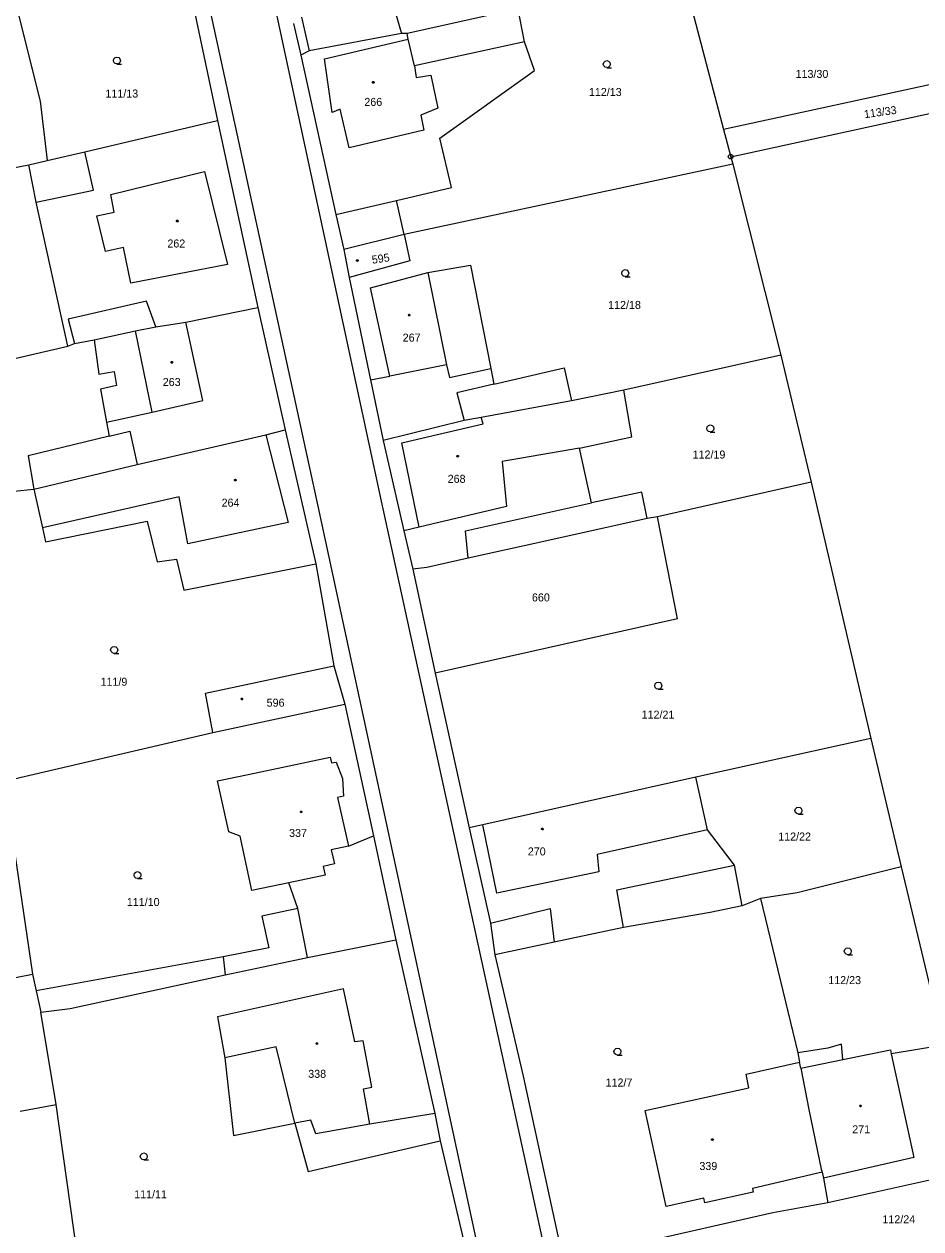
# Model space of a CAD drawing. Extents: x -757994 to -755874, y -1047691 to -1046119.
# Drawn here: x -756452.9 to -756357.8, y -1047170.3 to -1047042.4 of the extents above; entities that cross this region are included whole.
import ezdxf

# ---------------------------------------------------------------- set-up
doc = ezdxf.new("R2010")
doc.units = 0
doc.layers.add('katastrální mapa', color=7, linetype='Continuous')

msp = doc.modelspace()

# ---------------------------------------------------------------- linework, layer by layer
at = {"layer": 'katastrální mapa'}
for p, q in [((-756415, -1047093.07), (-756430.44, -1047021.1)), ((-756438.8, -1047022.23), (-756432.39, -1047052.66)), ((-756437.35, -1047021.83), (-756421.74, -1047093.61)), ((-756383.08, -1047037.05), (-756378.72, -1047053.6)), ((-756413.72, -1047040.53), (-756412.88, -1047043.43)), ((-756399.82, -1047044.31), (-756400.59, -1047040.49)), ((-756453.58, -1047041.15), (-756451.2, -1047050.59)), ((-756423.48, -1047041.7), (-756422.66, -1047045.25)), ((-756402.57, -1047041.28), (-756412.28, -1047043.41)), ((-756424.34, -1047042.36), (-756423.55, -1047045.74)), ((-756412.88, -1047043.43), (-756422.66, -1047045.25)), ((-756421.04, -1047046.13), (-756412.18, -1047044.01)), ((-756412.28, -1047043.41), (-756412.88, -1047043.43)), ((-756412.18, -1047044.01), (-756412.28, -1047043.41)), ((-756411.49, -1047046.87), (-756412.18, -1047044.01)), ((-756399.82, -1047044.31), (-756411.49, -1047046.87)), ((-756398.78, -1047047.34), (-756399.82, -1047044.31)), ((-756422.66, -1047045.25), (-756423.55, -1047045.74)), ((-756423.55, -1047045.74), (-756419.85, -1047062.65)), ((-756420.24, -1047051.8), (-756421.04, -1047046.13)), ((-756411.49, -1047046.87), (-756411.33, -1047048.08)), ((-756342.39, -1047045.7), (-756378.72, -1047053.6)), ((-756411.33, -1047048.08), (-756409.76, -1047047.84)), ((-756409.76, -1047047.84), (-756409.02, -1047051.35)), ((-756408.81, -1047054.52), (-756398.78, -1047047.34)), ((-756377.96, -1047056.5), (-756340.02, -1047048.25)), ((-756451.2, -1047050.59), (-756450.47, -1047056.91)), ((-756419.39, -1047051.46), (-756420.24, -1047051.8)), ((-756418.42, -1047055.57), (-756419.39, -1047051.46)), ((-756409.02, -1047051.35), (-756410.84, -1047052.1)), ((-756446.45, -1047056), (-756432.39, -1047052.66)), ((-756432.39, -1047052.66), (-756428.13, -1047072.51)), ((-756410.84, -1047052.1), (-756410.52, -1047053.67)), ((-756410.52, -1047053.67), (-756418.42, -1047055.57)), ((-756407.58, -1047059.77), (-756408.81, -1047054.52)), ((-756378.72, -1047053.6), (-756377.96, -1047056.5)), ((-756452.42, -1047057.35), (-756450.47, -1047056.91)), ((-756450.47, -1047056.91), (-756446.45, -1047056)), ((-756445.56, -1047060.06), (-756446.45, -1047056)), ((-756378.02, -1047056.5), (-756377.9, -1047056.5)), ((-756377.96, -1047056.5), (-756377.75, -1047057.29)), ((-756466.88, -1047060.21), (-756452.42, -1047057.35)), ((-756451.61, -1047061.33), (-756452.42, -1047057.35)), ((-756443.69, -1047060.51), (-756433.78, -1047058.06)), ((-756433.78, -1047058.06), (-756431.33, -1047067.93)), ((-756377.75, -1047057.29), (-756412.59, -1047064.77)), ((-756377.75, -1047057.29), (-756372.63, -1047077.56)), ((-756451.61, -1047061.33), (-756445.56, -1047060.06)), ((-756443.34, -1047062.4), (-756443.69, -1047060.51)), ((-756413.41, -1047061.14), (-756407.58, -1047059.77)), ((-756448.28, -1047076.61), (-756451.61, -1047061.33)), ((-756419.85, -1047062.65), (-756413.41, -1047061.14)), ((-756412.59, -1047064.77), (-756413.41, -1047061.14)), ((-756445.2, -1047062.79), (-756443.34, -1047062.4)), ((-756444.26, -1047066.58), (-756445.2, -1047062.79)), ((-756419.85, -1047062.65), (-756418.99, -1047066.35)), ((-756412.59, -1047064.77), (-756418.99, -1047066.35)), ((-756412.59, -1047064.77), (-756411.98, -1047067.55)), ((-756442.37, -1047066.15), (-756444.26, -1047066.58)), ((-756441.59, -1047069.93), (-756442.37, -1047066.15)), ((-756418.99, -1047066.35), (-756418.44, -1047069.33)), ((-756431.33, -1047067.93), (-756441.59, -1047069.93)), ((-756411.98, -1047067.55), (-756418.44, -1047069.33)), ((-756410.09, -1047068.8), (-756405.55, -1047068)), ((-756405.55, -1047068), (-756403.41, -1047078.99)), ((-756418.44, -1047069.33), (-756416.18, -1047080.19)), ((-756416.18, -1047070.43), (-756410.09, -1047068.8)), ((-756410.09, -1047068.8), (-756408.12, -1047078.58)), ((-756414.12, -1047079.78), (-756416.18, -1047070.43)), ((-756439.92, -1047071.82), (-756448.22, -1047073.75)), ((-756438.95, -1047074.57), (-756439.92, -1047071.82)), ((-756435.74, -1047074.06), (-756428.13, -1047072.51)), ((-756428.13, -1047072.51), (-756425.2, -1047085.48)), ((-756448.22, -1047073.75), (-756447.57, -1047076.33)), ((-756445.48, -1047075.95), (-756441.09, -1047074.99)), ((-756441.09, -1047074.99), (-756438.95, -1047074.57)), ((-756439.32, -1047083.61), (-756441.09, -1047074.99)), ((-756438.95, -1047074.57), (-756435.74, -1047074.06)), ((-756433.96, -1047082.39), (-756435.74, -1047074.06)), ((-756448.28, -1047076.61), (-756447.57, -1047076.33)), ((-756447.57, -1047076.33), (-756445.48, -1047075.95)), ((-756445.48, -1047075.95), (-756444.98, -1047079.57)), ((-756457.57, -1047078.78), (-756448.28, -1047076.61)), ((-756372.63, -1047077.56), (-756389.3, -1047081.3)), ((-756372.63, -1047077.56), (-756369.43, -1047091.04)), ((-756408.12, -1047078.58), (-756414.12, -1047079.78)), ((-756408.12, -1047078.58), (-756407.8, -1047079.95)), ((-756444.98, -1047079.57), (-756443.37, -1047079.29)), ((-756443.37, -1047079.29), (-756443.09, -1047080.78)), ((-756416.18, -1047080.19), (-756414.12, -1047079.78)), ((-756416.18, -1047080.19), (-756414.83, -1047086.64)), ((-756407.8, -1047079.95), (-756403.41, -1047078.99)), ((-756403.41, -1047078.99), (-756403.09, -1047080.66)), ((-756403.09, -1047080.66), (-756395.64, -1047078.92)), ((-756395.64, -1047078.92), (-756394.86, -1047082.43)), ((-756443.09, -1047080.78), (-756444.82, -1047081.17)), ((-756444.82, -1047081.17), (-756444.16, -1047084.67)), ((-756403.09, -1047080.66), (-756407, -1047081.57)), ((-756389.3, -1047081.3), (-756394.86, -1047082.43)), ((-756388.44, -1047086.25), (-756389.3, -1047081.3)), ((-756439.32, -1047083.61), (-756433.96, -1047082.39)), ((-756407, -1047081.57), (-756406.24, -1047084.52)), ((-756394.86, -1047082.43), (-756404.43, -1047084.17)), ((-756444.16, -1047084.67), (-756439.32, -1047083.61)), ((-756444.16, -1047084.67), (-756443.88, -1047086.15)), ((-756406.24, -1047084.52), (-756414.83, -1047086.64)), ((-756412.83, -1047086.89), (-756404.21, -1047084.85)), ((-756404.43, -1047084.17), (-756406.24, -1047084.52)), ((-756404.21, -1047084.85), (-756404.43, -1047084.17)), ((-756443.88, -1047086.15), (-756452.47, -1047088.24)), ((-756443.88, -1047086.15), (-756441.7, -1047085.62)), ((-756441.7, -1047085.62), (-756440.91, -1047089.19)), ((-756440.91, -1047089.19), (-756427.26, -1047086.02)), ((-756427.26, -1047086.02), (-756425.2, -1047085.48)), ((-756427.26, -1047086.02), (-756424.91, -1047095.32)), ((-756425.2, -1047085.48), (-756421.95, -1047099.73)), ((-756393.99, -1047087.45), (-756388.44, -1047086.25)), ((-756414.83, -1047086.64), (-756412.62, -1047096.2)), ((-756411, -1047095.82), (-756412.83, -1047086.89)), ((-756393.99, -1047087.45), (-756402.2, -1047088.86)), ((-756392.71, -1047093.25), (-756393.99, -1047087.45)), ((-756452.47, -1047088.24), (-756451.89, -1047091.78)), ((-756402.2, -1047088.86), (-756401.73, -1047093.64)), ((-756451.89, -1047091.78), (-756440.91, -1047089.19)), ((-756369.43, -1047091.04), (-756385.71, -1047094.72)), ((-756369.43, -1047091.04), (-756363.09, -1047118.27)), ((-756453.97, -1047092), (-756451.89, -1047091.78)), ((-756451.89, -1047091.78), (-756450.96, -1047095.89)), ((-756436.45, -1047092.6), (-756450.96, -1047095.89)), ((-756435.54, -1047097.59), (-756436.45, -1047092.6)), ((-756387.4, -1047092.11), (-756392.71, -1047093.25)), ((-756386.83, -1047094.89), (-756387.4, -1047092.11)), ((-756421.74, -1047093.61), (-756404.48, -1047173.68)), ((-756397.11, -1047175.01), (-756415, -1047093.07)), ((-756401.73, -1047093.64), (-756411, -1047095.82)), ((-756406.1, -1047096.2), (-756392.71, -1047093.25)), ((-756450.64, -1047097.38), (-756439.84, -1047095.19)), ((-756439.84, -1047095.19), (-756438.8, -1047099.5)), ((-756424.91, -1047095.32), (-756435.54, -1047097.59)), ((-756386.83, -1047094.89), (-756397.79, -1047097.35)), ((-756385.71, -1047094.72), (-756386.83, -1047094.89)), ((-756383.59, -1047105.55), (-756385.71, -1047094.72)), ((-756450.96, -1047095.89), (-756450.64, -1047097.38)), ((-756411, -1047095.82), (-756412.62, -1047096.2)), ((-756412.62, -1047096.2), (-756411.68, -1047100.29)), ((-756405.79, -1047099.1), (-756406.1, -1047096.2)), ((-756397.79, -1047097.35), (-756405.79, -1047099.1)), ((-756438.8, -1047099.5), (-756436.75, -1047099.24)), ((-756436.75, -1047099.24), (-756435.96, -1047102.5)), ((-756405.79, -1047099.1), (-756410.19, -1047100.09)), ((-756435.96, -1047102.5), (-756421.95, -1047099.73)), ((-756421.95, -1047099.73), (-756420.05, -1047110.55)), ((-756410.19, -1047100.09), (-756411.68, -1047100.29)), ((-756411.68, -1047100.29), (-756409.3, -1047111.32)), ((-756383.59, -1047105.55), (-756409.3, -1047111.32)), ((-756433.66, -1047113.46), (-756420.05, -1047110.55)), ((-756420.05, -1047110.55), (-756418.88, -1047114.62)), ((-756409.3, -1047111.32), (-756405.71, -1047127.74)), ((-756432.89, -1047117.63), (-756433.66, -1047113.46)), ((-756432.89, -1047117.63), (-756418.88, -1047114.62)), ((-756418.88, -1047114.62), (-756415.86, -1047128.6)), ((-756455.02, -1047122.79), (-756432.89, -1047117.63)), ((-756363.09, -1047118.27), (-756381.66, -1047122.36)), ((-756363.09, -1047118.27), (-756359.87, -1047131.89)), ((-756381.66, -1047122.36), (-756404.26, -1047127.42)), ((-756380.41, -1047127.96), (-756381.66, -1047122.36)), ((-756455.02, -1047122.79), (-756452.02, -1047143.28)), ((-756404.26, -1047127.42), (-756405.71, -1047127.74)), ((-756402.77, -1047134.67), (-756404.26, -1047127.42)), ((-756418.51, -1047129.68), (-756415.86, -1047128.6)), ((-756415.86, -1047128.6), (-756413.48, -1047139.62)), ((-756405.71, -1047127.74), (-756403.42, -1047137.85)), ((-756380.41, -1047127.96), (-756392.13, -1047130.56)), ((-756377.55, -1047131.72), (-756380.41, -1047127.96)), ((-756392.13, -1047130.56), (-756391.94, -1047132.41)), ((-756391.94, -1047132.41), (-756402.77, -1047134.67)), ((-756390.04, -1047134.34), (-756377.55, -1047131.72)), ((-756376.75, -1047136.03), (-756377.55, -1047131.72)), ((-756359.87, -1047131.89), (-756370.91, -1047134.63)), ((-756359.87, -1047131.89), (-756355.35, -1047150.82)), ((-756423.87, -1047136.29), (-756424.81, -1047133.57)), ((-756389.34, -1047138.32), (-756390.04, -1047134.34)), ((-756370.91, -1047134.63), (-756374.81, -1047135.24)), ((-756423.87, -1047136.29), (-756427.7, -1047137.11)), ((-756422.86, -1047141.52), (-756423.87, -1047136.29)), ((-756403.42, -1047137.85), (-756397.1, -1047136.3)), ((-756397.1, -1047136.3), (-756396.7, -1047139.89)), ((-756376.75, -1047136.03), (-756380.13, -1047136.73)), ((-756374.81, -1047135.24), (-756376.75, -1047136.03)), ((-756374.81, -1047135.24), (-756370.85, -1047151.63)), ((-756427.7, -1047137.11), (-756426.95, -1047140.49)), ((-756380.13, -1047136.73), (-756389.34, -1047138.32)), ((-756403.42, -1047137.85), (-756402.99, -1047141.23)), ((-756389.34, -1047138.32), (-756396.7, -1047139.89)), ((-756422.86, -1047141.52), (-756413.48, -1047139.62)), ((-756413.48, -1047139.62), (-756409.34, -1047158.06)), ((-756396.7, -1047139.89), (-756402.99, -1047141.23)), ((-756431.78, -1047141.44), (-756451.62, -1047145.06)), ((-756426.95, -1047140.49), (-756431.78, -1047141.44)), ((-756431.78, -1047141.44), (-756431.59, -1047143.36)), ((-756431.59, -1047143.36), (-756422.86, -1047141.52)), ((-756402.99, -1047141.23), (-756399.98, -1047154.11)), ((-756455.64, -1047143.98), (-756452.02, -1047143.28)), ((-756452.02, -1047143.28), (-756451.62, -1047145.06)), ((-756448.02, -1047146.91), (-756431.59, -1047143.36)), ((-756451.62, -1047145.06), (-756451.13, -1047147.3)), ((-756419.02, -1047144.83), (-756432.4, -1047147.82)), ((-756417.82, -1047150.46), (-756419.02, -1047144.83)), ((-756451.13, -1047147.3), (-756448.02, -1047146.91)), ((-756449.5, -1047157.11), (-756451.13, -1047147.3)), ((-756432.4, -1047147.82), (-756431.63, -1047152.16)), ((-756416.93, -1047150.36), (-756417.82, -1047150.46)), ((-756416.03, -1047155.27), (-756416.93, -1047150.36)), ((-756426.16, -1047150.99), (-756431.63, -1047152.16)), ((-756424.18, -1047159.09), (-756426.16, -1047150.99)), ((-756367.64, -1047151.12), (-756370.85, -1047151.63)), ((-756370.85, -1047151.63), (-756370.65, -1047152.62)), ((-756366.2, -1047150.7), (-756367.64, -1047151.12)), ((-756366.05, -1047152.34), (-756366.2, -1047150.7)), ((-756366.05, -1047152.34), (-756361.02, -1047151.3)), ((-756361.02, -1047151.3), (-756360.93, -1047151.73)), ((-756355.35, -1047150.82), (-756360.93, -1047151.73)), ((-756360.93, -1047151.73), (-756358.55, -1047162.72)), ((-756431.63, -1047152.16), (-756430.7, -1047160.39)), ((-756376.32, -1047153.89), (-756370.65, -1047152.62)), ((-756370.52, -1047153.26), (-756370.65, -1047152.62)), ((-756370.52, -1047153.26), (-756366.05, -1047152.34)), ((-756399.98, -1047154.11), (-756395.72, -1047173.64)), ((-756376.03, -1047155.33), (-756376.32, -1047153.89)), ((-756370.52, -1047153.26), (-756369.66, -1047157.63)), ((-756416.91, -1047155.45), (-756416.03, -1047155.27)), ((-756416.22, -1047159.19), (-756416.91, -1047155.45)), ((-756387.02, -1047157.75), (-756376.03, -1047155.33)), ((-756453.34, -1047157.81), (-756449.5, -1047157.11)), ((-756446.49, -1047178.44), (-756449.5, -1047157.11)), ((-756409.34, -1047158.06), (-756416.22, -1047159.19)), ((-756409.34, -1047158.06), (-756408.78, -1047160.95)), ((-756384.8, -1047167.92), (-756387.02, -1047157.75)), ((-756369.66, -1047157.63), (-756368.35, -1047163.99)), ((-756430.7, -1047160.39), (-756424.18, -1047159.09)), ((-756422.49, -1047158.78), (-756424.18, -1047159.09)), ((-756424.18, -1047159.09), (-756422.76, -1047164.21)), ((-756421.97, -1047160.23), (-756422.49, -1047158.78)), ((-756416.22, -1047159.19), (-756421.97, -1047160.23)), ((-756422.76, -1047164.21), (-756408.78, -1047160.95)), ((-756408.78, -1047160.95), (-756405.8, -1047173.57)), ((-756358.55, -1047162.72), (-756368.1, -1047164.92)), ((-756368.26, -1047164.31), (-756375.66, -1047166.01)), ((-756368.35, -1047163.99), (-756368.26, -1047164.31)), ((-756368.26, -1047164.31), (-756368.1, -1047164.92)), ((-756368.1, -1047164.92), (-756367.65, -1047167.53)), ((-756355.57, -1047164.86), (-756367.65, -1047167.53)), ((-756380.82, -1047167.05), (-756384.8, -1047167.92)), ((-756380.72, -1047167.54), (-756380.82, -1047167.05)), ((-756375.58, -1047166.43), (-756380.72, -1047167.54)), ((-756375.66, -1047166.01), (-756375.58, -1047166.43)), ((-756367.65, -1047167.53), (-756373.48, -1047168.61)), ((-756373.48, -1047168.61), (-756395.72, -1047173.64))]:
    msp.add_line(p, q, dxfattribs=at)
for points in [[(-756443.05, -1047046.66), (-756443.24, -1047046.61), (-756443.38, -1047046.48), (-756443.43, -1047046.29), (-756443.38, -1047046.11), (-756443.24, -1047045.97), (-756443.06, -1047045.92), (-756442.87, -1047045.97), (-756442.74, -1047046.11), (-756442.69, -1047046.3), (-756442.74, -1047046.49), (-756442.87, -1047046.62), (-756443.06, -1047046.67), (-756442.56, -1047046.67)], [(-756391.1, -1047047.04), (-756391.29, -1047046.99), (-756391.43, -1047046.86), (-756391.48, -1047046.67), (-756391.43, -1047046.49), (-756391.29, -1047046.35), (-756391.1, -1047046.3), (-756390.92, -1047046.35), (-756390.78, -1047046.49), (-756390.73, -1047046.68), (-756390.78, -1047046.87), (-756390.92, -1047047), (-756391.11, -1047047.05), (-756390.61, -1047047.05)], [(-756389.13, -1047069.23), (-756389.32, -1047069.18), (-756389.46, -1047069.04), (-756389.51, -1047068.86), (-756389.46, -1047068.68), (-756389.32, -1047068.54), (-756389.14, -1047068.49), (-756388.95, -1047068.54), (-756388.82, -1047068.68), (-756388.77, -1047068.87), (-756388.82, -1047069.05), (-756388.95, -1047069.19), (-756389.14, -1047069.24), (-756388.64, -1047069.24)], [(-756380.12, -1047085.72), (-756380.31, -1047085.67), (-756380.45, -1047085.53), (-756380.49, -1047085.35), (-756380.45, -1047085.17), (-756380.31, -1047085.03), (-756380.12, -1047084.98), (-756379.94, -1047085.03), (-756379.8, -1047085.17), (-756379.76, -1047085.36), (-756379.8, -1047085.54), (-756379.94, -1047085.68), (-756380.13, -1047085.73), (-756379.63, -1047085.73)], [(-756443.35, -1047109.23), (-756443.54, -1047109.18), (-756443.68, -1047109.04), (-756443.73, -1047108.86), (-756443.68, -1047108.68), (-756443.54, -1047108.54), (-756443.35, -1047108.49), (-756443.17, -1047108.54), (-756443.03, -1047108.68), (-756442.98, -1047108.87), (-756443.03, -1047109.05), (-756443.17, -1047109.19), (-756443.36, -1047109.24), (-756442.86, -1047109.24)], [(-756385.63, -1047113.02), (-756385.82, -1047112.97), (-756385.96, -1047112.84), (-756386.01, -1047112.65), (-756385.96, -1047112.47), (-756385.82, -1047112.33), (-756385.64, -1047112.28), (-756385.45, -1047112.33), (-756385.32, -1047112.47), (-756385.27, -1047112.66), (-756385.32, -1047112.85), (-756385.45, -1047112.98), (-756385.64, -1047113.03), (-756385.14, -1047113.03)], [(-756429.13, -1047122.07), (-756420.45, -1047120.23), (-756420.29, -1047120.85), (-756419.8, -1047120.76), (-756419.12, -1047122.49), (-756419.03, -1047124.38), (-756419.66, -1047124.52), (-756418.51, -1047129.68)], [(-756429.98, -1047128.63), (-756431.19, -1047128.16), (-756432.39, -1047122.76), (-756429.13, -1047122.07)], [(-756370.76, -1047126.28), (-756370.95, -1047126.23), (-756371.09, -1047126.1), (-756371.14, -1047125.91), (-756371.09, -1047125.73), (-756370.95, -1047125.59), (-756370.77, -1047125.54), (-756370.58, -1047125.59), (-756370.45, -1047125.73), (-756370.4, -1047125.92), (-756370.45, -1047126.11), (-756370.58, -1047126.24), (-756370.77, -1047126.29), (-756370.27, -1047126.29)], [(-756424.81, -1047133.57), (-756428.74, -1047134.38), (-756429.98, -1047128.63)], [(-756418.51, -1047129.68), (-756420.33, -1047130.09), (-756420, -1047131.57), (-756421.17, -1047131.83), (-756420.96, -1047132.78), (-756424.81, -1047133.57)], [(-756440.87, -1047133.12), (-756441.06, -1047133.07), (-756441.2, -1047132.94), (-756441.24, -1047132.75), (-756441.2, -1047132.57), (-756441.06, -1047132.43), (-756440.88, -1047132.38), (-756440.69, -1047132.43), (-756440.55, -1047132.57), (-756440.51, -1047132.76), (-756440.55, -1047132.95), (-756440.69, -1047133.08), (-756440.88, -1047133.13), (-756440.38, -1047133.13)], [(-756365.53, -1047141.21), (-756365.72, -1047141.16), (-756365.85, -1047141.02), (-756365.91, -1047140.84), (-756365.85, -1047140.66), (-756365.72, -1047140.52), (-756365.54, -1047140.47), (-756365.35, -1047140.52), (-756365.22, -1047140.66), (-756365.17, -1047140.85), (-756365.22, -1047141.03), (-756365.35, -1047141.17), (-756365.54, -1047141.22), (-756365.04, -1047141.22)], [(-756389.97, -1047151.86), (-756390.16, -1047151.81), (-756390.29, -1047151.68), (-756390.35, -1047151.49), (-756390.29, -1047151.3), (-756390.16, -1047151.17), (-756389.98, -1047151.12), (-756389.79, -1047151.17), (-756389.66, -1047151.3), (-756389.6, -1047151.49), (-756389.66, -1047151.69), (-756389.79, -1047151.82), (-756389.98, -1047151.87), (-756389.48, -1047151.87)], [(-756440.21, -1047162.99), (-756440.4, -1047162.94), (-756440.53, -1047162.8), (-756440.59, -1047162.62), (-756440.53, -1047162.44), (-756440.4, -1047162.3), (-756440.22, -1047162.25), (-756440.03, -1047162.3), (-756439.9, -1047162.44), (-756439.85, -1047162.62), (-756439.9, -1047162.82), (-756440.03, -1047162.95), (-756440.22, -1047163), (-756439.72, -1047163)]]:
    msp.add_lwpolyline(points, dxfattribs=at)
for points in [[(-756415.87, -1047048.52), (-756415.82, -1047048.53), (-756415.79, -1047048.58), (-756415.78, -1047048.61), (-756415.79, -1047048.66), (-756415.84, -1047048.69), (-756415.87, -1047048.7), (-756415.92, -1047048.68), (-756415.95, -1047048.65), (-756415.96, -1047048.61), (-756415.95, -1047048.57), (-756415.91, -1047048.53)], [(-756377.89, -1047056.26), (-756377.76, -1047056.35), (-756377.71, -1047056.49), (-756377.76, -1047056.64), (-756377.89, -1047056.73), (-756378.04, -1047056.73), (-756378.17, -1047056.64), (-756378.22, -1047056.49), (-756378.17, -1047056.35), (-756378.04, -1047056.26)], [(-756436.65, -1047063.24), (-756436.6, -1047063.25), (-756436.58, -1047063.3), (-756436.57, -1047063.33), (-756436.58, -1047063.38), (-756436.61, -1047063.41), (-756436.65, -1047063.42), (-756436.7, -1047063.4), (-756436.73, -1047063.37), (-756436.74, -1047063.33), (-756436.73, -1047063.28), (-756436.69, -1047063.25)], [(-756417.56, -1047067.44), (-756417.51, -1047067.45), (-756417.49, -1047067.49), (-756417.48, -1047067.52), (-756417.49, -1047067.57), (-756417.53, -1047067.6), (-756417.56, -1047067.61), (-756417.6, -1047067.59), (-756417.64, -1047067.56), (-756417.65, -1047067.52), (-756417.64, -1047067.48), (-756417.6, -1047067.44)], [(-756412.07, -1047073.23), (-756412.02, -1047073.24), (-756411.99, -1047073.28), (-756411.98, -1047073.31), (-756411.99, -1047073.36), (-756412.03, -1047073.39), (-756412.07, -1047073.4), (-756412.11, -1047073.38), (-756412.15, -1047073.35), (-756412.16, -1047073.31), (-756412.15, -1047073.27), (-756412.1, -1047073.23)], [(-756437.23, -1047078.24), (-756437.18, -1047078.25), (-756437.16, -1047078.3), (-756437.15, -1047078.33), (-756437.16, -1047078.38), (-756437.2, -1047078.41), (-756437.23, -1047078.42), (-756437.27, -1047078.4), (-756437.3, -1047078.37), (-756437.32, -1047078.33), (-756437.3, -1047078.28), (-756437.26, -1047078.25)], [(-756406.91, -1047088.21), (-756406.86, -1047088.22), (-756406.84, -1047088.26), (-756406.83, -1047088.29), (-756406.84, -1047088.34), (-756406.88, -1047088.37), (-756406.91, -1047088.38), (-756406.96, -1047088.36), (-756406.99, -1047088.33), (-756407, -1047088.29), (-756406.99, -1047088.25), (-756406.95, -1047088.21)], [(-756430.5, -1047090.74), (-756430.45, -1047090.75), (-756430.43, -1047090.8), (-756430.42, -1047090.83), (-756430.43, -1047090.88), (-756430.47, -1047090.91), (-756430.5, -1047090.92), (-756430.54, -1047090.9), (-756430.58, -1047090.87), (-756430.59, -1047090.83), (-756430.58, -1047090.78), (-756430.53, -1047090.75)], [(-756429.81, -1047113.98), (-756429.76, -1047113.99), (-756429.74, -1047114.03), (-756429.73, -1047114.06), (-756429.74, -1047114.11), (-756429.78, -1047114.14), (-756429.81, -1047114.15), (-756429.85, -1047114.13), (-756429.89, -1047114.1), (-756429.9, -1047114.06), (-756429.89, -1047114.02), (-756429.85, -1047113.98)], [(-756423.53, -1047125.96), (-756423.48, -1047125.97), (-756423.46, -1047126.01), (-756423.45, -1047126.04), (-756423.46, -1047126.09), (-756423.5, -1047126.12), (-756423.53, -1047126.12), (-756423.58, -1047126.11), (-756423.6, -1047126.08), (-756423.61, -1047126.04), (-756423.6, -1047126), (-756423.57, -1047125.96)], [(-756397.93, -1047127.77), (-756397.88, -1047127.78), (-756397.85, -1047127.83), (-756397.85, -1047127.86), (-756397.85, -1047127.91), (-756397.9, -1047127.94), (-756397.93, -1047127.95), (-756397.98, -1047127.93), (-756398.01, -1047127.9), (-756398.02, -1047127.86), (-756398.01, -1047127.82), (-756397.97, -1047127.78)], [(-756421.86, -1047150.55), (-756421.81, -1047150.57), (-756421.78, -1047150.61), (-756421.77, -1047150.64), (-756421.78, -1047150.69), (-756421.83, -1047150.72), (-756421.86, -1047150.73), (-756421.91, -1047150.71), (-756421.94, -1047150.68), (-756421.95, -1047150.64), (-756421.94, -1047150.6), (-756421.9, -1047150.56)], [(-756364.19, -1047157.18), (-756364.14, -1047157.19), (-756364.11, -1047157.23), (-756364.1, -1047157.26), (-756364.11, -1047157.3), (-756364.16, -1047157.34), (-756364.19, -1047157.35), (-756364.23, -1047157.33), (-756364.26, -1047157.3), (-756364.27, -1047157.26), (-756364.26, -1047157.22), (-756364.22, -1047157.18)], [(-756379.9, -1047160.74), (-756379.85, -1047160.75), (-756379.83, -1047160.8), (-756379.82, -1047160.83), (-756379.83, -1047160.88), (-756379.86, -1047160.91), (-756379.9, -1047160.92), (-756379.95, -1047160.9), (-756379.98, -1047160.87), (-756379.99, -1047160.83), (-756379.98, -1047160.78), (-756379.94, -1047160.75)]]:
    msp.add_lwpolyline(points, close=True, dxfattribs=at)

# ---------------------------------------------------------------- texts
for s, p in [('113/30', (-756371.08, -1047048.14)), ('111/13', (-756444.28, -1047050.22)), ('112/13', (-756393, -1047050.06)), ('266', (-756416.82, -1047051.11)), ('262', (-756437.71, -1047066.14)), ('112/18', (-756390.96, -1047072.66)), ('267', (-756412.75, -1047076.13)), ('263', (-756438.2, -1047080.84)), ('112/19', (-756382, -1047088.54)), ('268', (-756407.98, -1047091.12)), ('264', (-756431.96, -1047093.65)), ('660', (-756399.04, -1047103.71)), ('111/9', (-756444.8, -1047112.66)), ('596', (-756427.18, -1047114.88)), ('112/21', (-756387.41, -1047116.15)), ('337', (-756424.8, -1047128.71)), ('112/22', (-756372.92, -1047129.09)), ('270', (-756399.48, -1047130.67)), ('111/10', (-756442.01, -1047136.04)), ('112/23', (-756367.61, -1047144.33)), ('338', (-756422.77, -1047154.28)), ('112/7', (-756391.23, -1047155.2)), ('271', (-756365.07, -1047160.17)), ('339', (-756381.28, -1047164.06)), ('111/11', (-756441.23, -1047167.07)), ('112/24', (-756361.87, -1047169.72))]:
    msp.add_text(s, height=0.85, dxfattribs=at).set_placement(p)
for s, rotation, p in [('113/33', 7.9068, (-756363.76, -1047052.42)), ('595', 8.4225, (-756415.96, -1047067.87))]:
    msp.add_text(s, height=0.85, rotation=rotation, dxfattribs=at).set_placement(p)

doc.saveas('drawing.dxf')
